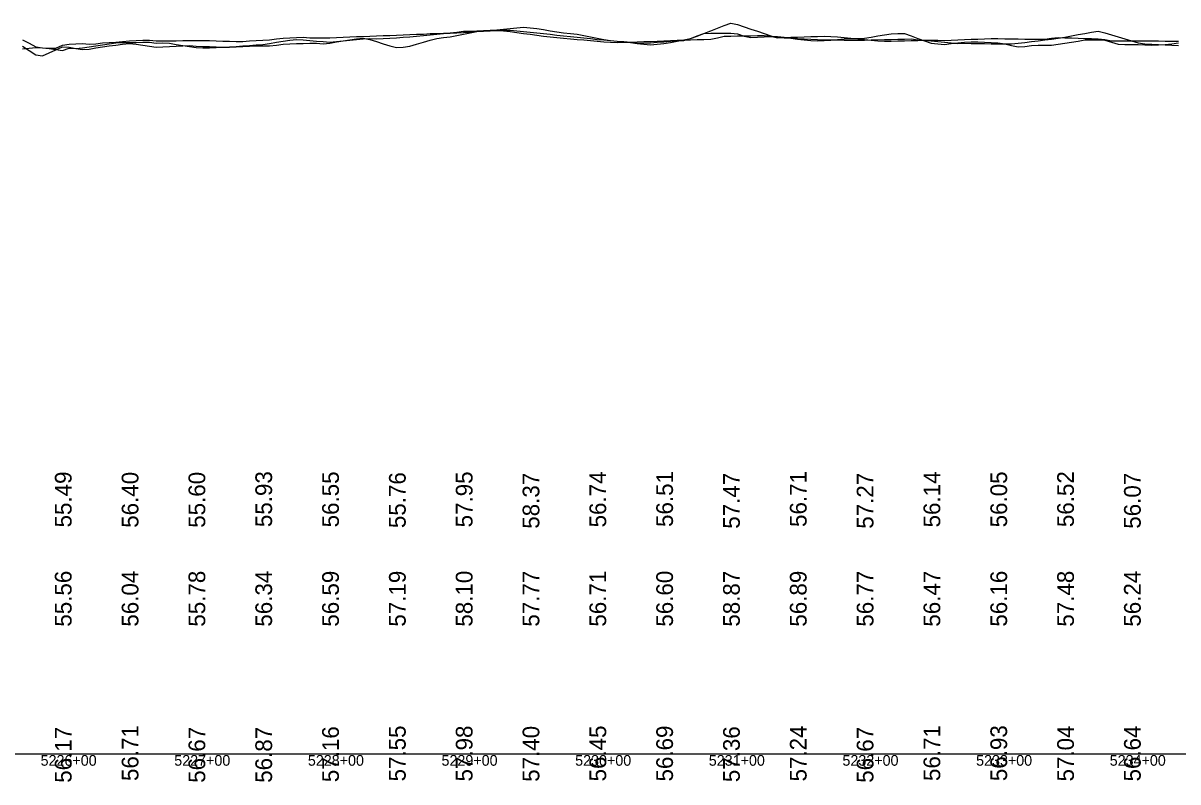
# Model space of a CAD drawing. Extents: x 2147288 to 2220488, y 740833 to 759333.
# Drawn here: x 2204944 to 2205808, y 750062 to 750630 of the extents above; entities that cross this region are included whole.
import ezdxf

# ---------------------------------------------------------------- set-up
doc = ezdxf.new("R2010")
doc.units = 0
for name, color, linetype in [('RD_DDB_Profile_EX', 7, 'Continuous'), ('RD_DDB_StaTX', 7, 'Continuous'), ('RD_DDB_StripGrade', 7, 'Continuous'), ('RD_GPK_Profile_Cell', 7, 'Continuous')]:
    doc.layers.add(name, color=color, linetype=linetype)

msp = doc.modelspace()

# ---------------------------------------------------------------- linework, layer by layer
at = {"layer": 'RD_DDB_Profile_EX'}
for points in [[(2205038.28, 750612.58), (2205043.28, 750611.86), (2205048.28, 750611.99), (2205053.28, 750612.26), (2205058.28, 750612.53), (2205063.28, 750612.8), (2205068.28, 750613), (2205073.28, 750612.65), (2205078.28, 750612.43), (2205083.28, 750612.22), (2205088.28, 750612), (2205093.28, 750611.79), (2205098.28, 750612.01), (2205103.28, 750612.37), (2205108.28, 750612.73), (2205113.28, 750613.09), (2205118.28, 750613.46), (2205123.28, 750613.88), (2205128.28, 750614.68), (2205133.28, 750615.48), (2205138.28, 750616.28), (2205143.28, 750617.08), (2205148.28, 750617.6), (2205153.28, 750617.2), (2205158.28, 750616.81), (2205163.28, 750616.42), (2205168.28, 750616.03), (2205173.28, 750615.64), (2205178.28, 750616.12), (2205183.28, 750616.58), (2205188.28, 750617.04), (2205193.28, 750617.49), (2205198.28, 750617.95), (2205203.28, 750618.41), (2205208.28, 750618.08), (2205213.28, 750618.37), (2205218.28, 750618.65), (2205223.28, 750618.93), (2205228.28, 750619.21), (2205233.28, 750619.5), (2205238.28, 750620.17), (2205243.28, 750620.67), (2205248.28, 750621.16), (2205253.28, 750621.66), (2205258.28, 750622.15), (2205263.28, 750622.65), (2205268.28, 750623.14), (2205273.28, 750623.73), (2205278.28, 750623.87), (2205283.28, 750624.01), (2205288.28, 750624.15), (2205293.28, 750624.3), (2205298.28, 750624.44), (2205303.28, 750624.58), (2205308.28, 750624.56), (2205313.28, 750624.06), (2205318.28, 750623.56), (2205323.28, 750623.05), (2205328.28, 750622.55), (2205333.28, 750622.05), (2205338.28, 750621.5), (2205343.28, 750620.92), (2205348.28, 750620.41), (2205353.28, 750619.91), (2205358.28, 750619.41), (2205363.28, 750618.91), (2205368.28, 750618.4), (2205373.28, 750617.65), (2205378.28, 750617.21), (2205383.28, 750616.81), (2205388.28, 750616.4), (2205393.28, 750615.99), (2205398.28, 750615.59), (2205403.28, 750615.18), (2205408.28, 750614.83), (2205413.28, 750615.17), (2205418.28, 750615.52), (2205423.28, 750615.86), (2205428.28, 750616.21), (2205433.28, 750616.56), (2205438.28, 750616.9), (2205443.28, 750618.26), (2205448.28, 750620.21), (2205453.28, 750622.16), (2205458.28, 750624.12), (2205463.28, 750626.07), (2205468.28, 750628.02), (2205473.28, 750629.82), (2205478.28, 750628.69), (2205483.28, 750627.03), (2205488.28, 750625.37), (2205493.28, 750623.71), (2205498.28, 750622.06), (2205503.28, 750620.4), (2205508.28, 750619.15), (2205513.28, 750618.81), (2205518.28, 750618.54), (2205523.28, 750618.28), (2205528.28, 750618.01), (2205533.28, 750617.75), (2205538.28, 750617.48)], [(2205038.28, 750615.46), (2205043.28, 750614.74), (2205048.28, 750614.96), (2205053.28, 750614.71), (2205058.28, 750613.93), (2205063.28, 750613.15), (2205068.28, 750612.36), (2205073.28, 750611.62), (2205078.28, 750611.4), (2205083.28, 750611.41), (2205088.28, 750611.56), (2205093.28, 750611.71), (2205098.28, 750611.86), (2205103.28, 750612.06), (2205108.28, 750612.42), (2205113.28, 750612.6), (2205118.28, 750612.71), (2205123.28, 750612.81), (2205128.28, 750612.91), (2205133.28, 750613.23), (2205138.28, 750614.02), (2205143.28, 750614.33), (2205148.28, 750614.47), (2205153.28, 750614.61), (2205158.28, 750614.75), (2205163.28, 750614.7), (2205168.28, 750614.31), (2205173.28, 750614.88), (2205178.28, 750615.71), (2205183.28, 750616.54), (2205188.28, 750617.37), (2205193.28, 750618.08), (2205198.28, 750618.54), (2205203.28, 750617.61), (2205208.28, 750615.99), (2205213.28, 750614.38), (2205218.28, 750612.76), (2205223.28, 750611.57), (2205228.28, 750611.86), (2205233.28, 750612.52), (2205238.28, 750613.99), (2205243.28, 750615.46), (2205248.28, 750616.94), (2205253.28, 750618.41), (2205258.28, 750619.05), (2205263.28, 750619.55), (2205268.28, 750620.56), (2205273.28, 750621.59), (2205278.28, 750622.62), (2205283.28, 750623.65), (2205288.28, 750624.28), (2205293.28, 750624.42), (2205298.28, 750624.8), (2205303.28, 750625.32), (2205308.28, 750625.84), (2205313.28, 750626.37), (2205318.28, 750626.8), (2205323.28, 750626.3), (2205328.28, 750625.7), (2205333.28, 750624.92), (2205338.28, 750624.13), (2205343.28, 750623.34), (2205348.28, 750622.56), (2205353.28, 750621.99), (2205358.28, 750621.48), (2205363.28, 750620.48), (2205368.28, 750619.49), (2205373.28, 750618.5), (2205378.28, 750617.5), (2205383.28, 750616.79), (2205388.28, 750616.39), (2205393.28, 750615.87), (2205398.28, 750615.27), (2205403.28, 750614.68), (2205408.28, 750614.08), (2205413.28, 750613.62), (2205418.28, 750613.96), (2205423.28, 750614.47), (2205428.28, 750615.42), (2205433.28, 750616.37), (2205438.28, 750617.33), (2205443.28, 750618.28), (2205448.28, 750620), (2205453.28, 750621.95), (2205458.28, 750622.24), (2205463.28, 750622.28), (2205468.28, 750622.32), (2205473.28, 750622.35), (2205478.28, 750621.73), (2205483.28, 750620.07), (2205488.28, 750619.16), (2205493.28, 750619.34), (2205498.28, 750619.51), (2205503.28, 750619.69), (2205508.28, 750619.86), (2205513.28, 750619.2), (2205518.28, 750618.54), (2205523.28, 750617.88), (2205528.28, 750617.22), (2205533.28, 750616.81), (2205538.28, 750616.54)], [(2204943.28, 750617.3), (2204948.28, 750614.78), (2204953.28, 750612.19), (2204958.28, 750611.45), (2204963.28, 750610.71), (2204968.28, 750609.97), (2204973.28, 750609.24), (2204978.28, 750611.07), (2204983.28, 750610.74), (2204988.28, 750611.43), (2204993.28, 750612.16), (2204998.28, 750612.89), (2205003.28, 750613.61), (2205008.28, 750614.34), (2205013.28, 750614.97), (2205018.28, 750615.27), (2205023.28, 750615.34), (2205028.28, 750615.41), (2205033.28, 750615.48), (2205038.28, 750615.46)], [(2204943.28, 750610.51), (2204948.28, 750611.09), (2204953.28, 750611.59), (2204958.28, 750611.38), (2204963.28, 750611.16), (2204968.28, 750611.18), (2204973.28, 750613.4), (2204978.28, 750614.13), (2204983.28, 750614.4), (2204988.28, 750614.67), (2204993.28, 750614.16), (2204998.28, 750614.42), (2205003.28, 750614.98), (2205008.28, 750615.33), (2205013.28, 750615.68), (2205018.28, 750616.15), (2205023.28, 750616.56), (2205028.28, 750616.82), (2205033.28, 750617.08), (2205038.28, 750617.1)], [(2205038.28, 750617.1), (2205043.28, 750616.48), (2205048.28, 750616.51), (2205053.28, 750616.55), (2205058.28, 750616.59), (2205063.28, 750616.82), (2205068.28, 750616.9), (2205073.28, 750616.85), (2205078.28, 750616.81), (2205083.28, 750616.73), (2205088.28, 750616.52), (2205093.28, 750616.37), (2205098.28, 750616.23), (2205103.28, 750616.08), (2205108.28, 750616.16), (2205113.28, 750616.5), (2205118.28, 750616.79), (2205123.28, 750617.09), (2205128.28, 750617.38), (2205133.28, 750618.08), (2205138.28, 750618.54), (2205143.28, 750618.79), (2205148.28, 750619.05), (2205153.28, 750619.21), (2205158.28, 750618.84), (2205163.28, 750618.82), (2205168.28, 750618.8), (2205173.28, 750618.78), (2205178.28, 750619.03), (2205183.28, 750619.38), (2205188.28, 750619.56), (2205193.28, 750619.74), (2205198.28, 750619.92), (2205203.28, 750620.1), (2205208.28, 750620.28), (2205213.28, 750620.46), (2205218.28, 750620.64), (2205223.28, 750620.82), (2205228.28, 750621.06), (2205233.28, 750621.26), (2205238.28, 750621.45), (2205243.28, 750621.63), (2205248.28, 750622.03), (2205253.28, 750622.16), (2205258.28, 750622.27), (2205263.28, 750622.37), (2205268.28, 750622.54), (2205273.28, 750622.85), (2205278.28, 750623.15), (2205283.28, 750623.46), (2205288.28, 750623.76), (2205293.28, 750624.07), (2205298.28, 750624.32), (2205303.28, 750624.08), (2205308.28, 750623.43), (2205313.28, 750622.77), (2205318.28, 750622.11), (2205323.28, 750621.46), (2205328.28, 750620.8), (2205333.28, 750620.15), (2205338.28, 750619.52), (2205343.28, 750619.02), (2205348.28, 750618.55), (2205353.28, 750618.12), (2205358.28, 750617.68), (2205363.28, 750617.24), (2205368.28, 750616.8), (2205373.28, 750616.36), (2205378.28, 750615.92), (2205383.28, 750615.5), (2205388.28, 750615.32), (2205393.28, 750615.48), (2205398.28, 750615.64), (2205403.28, 750615.8), (2205408.28, 750615.96), (2205413.28, 750616.12), (2205418.28, 750616.28), (2205423.28, 750616.53), (2205428.28, 750616.8), (2205433.28, 750616.97), (2205438.28, 750617.13), (2205443.28, 750617.29), (2205448.28, 750617.45), (2205453.28, 750617.62), (2205458.28, 750617.78), (2205463.28, 750618.77), (2205468.28, 750620.04), (2205473.28, 750620.12), (2205478.28, 750620.2), (2205483.28, 750620.29), (2205488.28, 750620.37), (2205493.28, 750620.45), (2205498.28, 750620.54), (2205503.28, 750619.96), (2205508.28, 750618.89), (2205513.28, 750619.06), (2205518.28, 750619.22), (2205523.28, 750619.39), (2205528.28, 750619.55), (2205533.28, 750619.72), (2205538.28, 750619.88)], [(2205538.28, 750617.48), (2205543.28, 750617.28), (2205548.28, 750617.33), (2205553.28, 750617.26), (2205558.28, 750617.18), (2205563.28, 750617.11), (2205568.28, 750617.04), (2205573.28, 750616.97), (2205578.28, 750617.19), (2205583.28, 750617.33), (2205588.28, 750617.47), (2205593.28, 750617.6), (2205598.28, 750617.74), (2205603.28, 750617.88), (2205608.28, 750618.02), (2205613.28, 750617.42), (2205618.28, 750616.96), (2205623.28, 750616.5), (2205628.28, 750616.05), (2205633.28, 750615.59), (2205638.28, 750615.14), (2205643.28, 750614.68), (2205648.28, 750614.71), (2205653.28, 750614.64), (2205658.28, 750614.56), (2205663.28, 750614.48), (2205668.28, 750614.41), (2205673.28, 750614.33), (2205678.28, 750614.24), (2205683.28, 750614.25), (2205688.28, 750614.84), (2205693.28, 750615.43), (2205698.28, 750616.02), (2205703.28, 750616.61), (2205708.28, 750617.21), (2205713.28, 750617.73), (2205718.28, 750618.49), (2205723.28, 750619.4), (2205728.28, 750620.32), (2205733.28, 750621.23), (2205738.28, 750622.15), (2205743.28, 750623.07), (2205748.28, 750623.81), (2205753.28, 750622.48), (2205758.28, 750621), (2205763.28, 750619.51), (2205768.28, 750618.03), (2205773.28, 750616.55), (2205778.28, 750615.06), (2205783.28, 750614.26), (2205788.28, 750614.03), (2205793.28, 750613.81), (2205798.28, 750613.59), (2205803.28, 750613.37), (2205808.28, 750613.15)], [(2205538.28, 750616.54), (2205543.28, 750616.72), (2205548.28, 750617.16), (2205553.28, 750617.6), (2205558.28, 750618.03), (2205563.28, 750618.31), (2205568.28, 750618.24), (2205573.28, 750618.45), (2205578.28, 750619.31), (2205583.28, 750620.18), (2205588.28, 750621.04), (2205593.28, 750621.86), (2205598.28, 750622), (2205603.28, 750622.06), (2205608.28, 750620.23), (2205613.28, 750618.4), (2205618.28, 750616.57), (2205623.28, 750614.81), (2205628.28, 750614.36), (2205633.28, 750613.94), (2205638.28, 750614.51), (2205643.28, 750615.09), (2205648.28, 750615.66), (2205653.28, 750615.79), (2205658.28, 750615.72), (2205663.28, 750615.54), (2205668.28, 750615.31), (2205673.28, 750615.08), (2205678.28, 750614.25), (2205683.28, 750613.19), (2205688.28, 750612.13), (2205693.28, 750612.38), (2205698.28, 750612.97), (2205703.28, 750613.21), (2205708.28, 750613.3), (2205713.28, 750613.4), (2205718.28, 750614.02), (2205723.28, 750614.76), (2205728.28, 750615.49), (2205733.28, 750616.4), (2205738.28, 750617.32), (2205743.28, 750617.36), (2205748.28, 750617.29), (2205753.28, 750617.06), (2205758.28, 750615.58), (2205763.28, 750614.09), (2205768.28, 750613.79), (2205773.28, 750613.84), (2205778.28, 750613.89), (2205783.28, 750613.66), (2205788.28, 750613.44), (2205793.28, 750613.48), (2205798.28, 750613.84), (2205803.28, 750614.2), (2205808.28, 750614.97)], [(2205538.28, 750619.88), (2205543.28, 750619.94), (2205548.28, 750619.74), (2205553.28, 750619.51), (2205558.28, 750619.01), (2205563.28, 750618.52), (2205568.28, 750618.02), (2205573.28, 750617.53), (2205578.28, 750617.03), (2205583.28, 750616.54), (2205588.28, 750616.23), (2205593.28, 750616.36), (2205598.28, 750616.49), (2205603.28, 750616.62), (2205608.28, 750616.74), (2205613.28, 750616.87), (2205618.28, 750616.99), (2205623.28, 750617.12), (2205628.28, 750617.15), (2205633.28, 750616.86), (2205638.28, 750617.07), (2205643.28, 750617.28), (2205648.28, 750617.49), (2205653.28, 750617.7), (2205658.28, 750617.91), (2205663.28, 750618.12), (2205668.28, 750618.27), (2205673.28, 750618.19), (2205678.28, 750618.11), (2205683.28, 750618.04), (2205688.28, 750617.97), (2205693.28, 750617.89), (2205698.28, 750617.82), (2205703.28, 750617.74), (2205708.28, 750617.79), (2205713.28, 750618.48), (2205718.28, 750618.97), (2205723.28, 750618.83), (2205728.28, 750618.69), (2205733.28, 750618.56), (2205738.28, 750618.42), (2205743.28, 750618.28), (2205748.28, 750618.14), (2205753.28, 750617.57), (2205758.28, 750616.66), (2205763.28, 750616.65), (2205768.28, 750616.65), (2205773.28, 750616.64), (2205778.28, 750616.63), (2205783.28, 750616.62), (2205788.28, 750616.61), (2205793.28, 750616.55), (2205798.28, 750616.4), (2205803.28, 750616.41), (2205808.28, 750616.41)], [(2204943.28, 750612.58), (2204948.28, 750609.33), (2204953.28, 750606.08), (2204958.28, 750605.28), (2204963.28, 750607.5), (2204968.28, 750609.73), (2204973.28, 750611.96), (2204978.28, 750611.71), (2204983.28, 750610.89), (2204988.28, 750610.07), (2204993.28, 750610.42), (2204998.28, 750611.28), (2205003.28, 750612.15), (2205008.28, 750612.87), (2205013.28, 750613.42), (2205018.28, 750613.97), (2205023.28, 750614.49), (2205028.28, 750614.01), (2205033.28, 750613.29), (2205038.28, 750612.58)]]:
    msp.add_lwpolyline(points, dxfattribs=at)
at = {"layer": 'RD_GPK_Profile_Cell'}
msp.add_line((2198888.28, 750083.43), (2220488.28, 750083.43), dxfattribs=at)

# ---------------------------------------------------------------- texts
at = {"layer": 'RD_DDB_Profile_EX'}
for s, p in [('55.49', (2204980.08, 750252.64)), ('56.40', (2205030.08, 750252.38)), ('55.60', (2205080.08, 750252.38)), ('55.93', (2205130.08, 750252.89)), ('56.55', (2205180.08, 750252.69)), ('55.76', (2205230.08, 750252.13)), ('57.95', (2205280.08, 750252.69)), ('58.37', (2205330.08, 750251.67)), ('56.74', (2205380.08, 750252.66)), ('56.51', (2205430.08, 750253)), ('57.47', (2205480.08, 750251.67)), ('56.71', (2205530.08, 750253)), ('57.27', (2205580.08, 750251.67)), ('56.14', (2205630.08, 750252.66)), ('56.05', (2205680.08, 750252.69)), ('56.52', (2205730.08, 750252.89)), ('56.07', (2205780.08, 750251.67)), ('56.17', (2204980.08, 750061.67)), ('56.71', (2205030.08, 750063)), ('56.67', (2205080.08, 750061.67)), ('56.87', (2205130.08, 750061.67)), ('57.16', (2205180.08, 750062.13)), ('57.55', (2205230.08, 750062.69)), ('57.98', (2205280.08, 750062.64)), ('57.40', (2205330.08, 750062.38)), ('56.45', (2205380.08, 750062.69)), ('56.69', (2205430.08, 750062.64)), ('57.36', (2205480.08, 750062.13)), ('57.24', (2205530.08, 750062.66)), ('56.67', (2205580.08, 750061.67)), ('56.71', (2205630.08, 750063)), ('56.93', (2205680.08, 750062.89)), ('57.04', (2205730.08, 750062.66)), ('56.64', (2205780.08, 750062.66))]:
    msp.add_text(s, height=12.5, rotation=90, dxfattribs=at).set_placement(p)
at = {"layer": 'RD_DDB_StaTX'}
for s, p in [('5226+00', (2204956.88, 750074.43)), ('5226+00', (2204956.88, 750074.43)), ('5226+00', (2204956.88, 750074.43)), ('5227+00', (2205056.88, 750074.43)), ('5227+00', (2205056.88, 750074.43)), ('5227+00', (2205056.88, 750074.43)), ('5228+00', (2205156.88, 750074.43)), ('5228+00', (2205156.88, 750074.43)), ('5228+00', (2205156.88, 750074.43)), ('5229+00', (2205256.88, 750074.43)), ('5229+00', (2205256.88, 750074.43)), ('5229+00', (2205256.88, 750074.43)), ('5230+00', (2205356.88, 750074.43)), ('5230+00', (2205356.88, 750074.43)), ('5230+00', (2205356.88, 750074.43)), ('5231+00', (2205456.88, 750074.43)), ('5231+00', (2205456.88, 750074.43)), ('5231+00', (2205456.88, 750074.43)), ('5232+00', (2205556.88, 750074.43)), ('5232+00', (2205556.88, 750074.43)), ('5232+00', (2205556.88, 750074.43)), ('5233+00', (2205656.88, 750074.43)), ('5233+00', (2205656.88, 750074.43)), ('5233+00', (2205656.88, 750074.43)), ('5234+00', (2205756.88, 750074.43)), ('5234+00', (2205756.88, 750074.43)), ('5234+00', (2205756.88, 750074.43))]:
    msp.add_text(s, height=8, dxfattribs=at).set_placement(p)
at = {"layer": 'RD_DDB_StripGrade'}
for s, p in [('55.56', (2204980.08, 750178.43)), ('56.04', (2205030.08, 750178.43)), ('55.78', (2205080.08, 750178.43)), ('56.34', (2205130.08, 750178.43)), ('56.59', (2205180.08, 750178.43)), ('57.19', (2205230.08, 750178.43)), ('58.10', (2205280.08, 750178.43)), ('57.77', (2205330.08, 750178.43)), ('56.71', (2205380.08, 750178.43)), ('56.60', (2205430.08, 750178.43)), ('58.87', (2205480.08, 750178.43)), ('56.89', (2205530.08, 750178.43)), ('56.77', (2205580.08, 750178.43)), ('56.47', (2205630.08, 750178.43)), ('56.16', (2205680.08, 750178.43)), ('57.48', (2205730.08, 750178.43)), ('56.24', (2205780.08, 750178.43))]:
    msp.add_text(s, height=12.5, rotation=90, dxfattribs=at).set_placement(p)

doc.saveas('drawing.dxf')
